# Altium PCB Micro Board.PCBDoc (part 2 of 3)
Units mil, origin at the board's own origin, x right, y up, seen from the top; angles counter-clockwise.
Board outline 8525 x 5525 mil, 2 copper layers (Top Layer, Bottom Layer); 82 components, 533 nets, 1257 pads, 165 vias.
Unrouted connection lines stored in the file: 4.
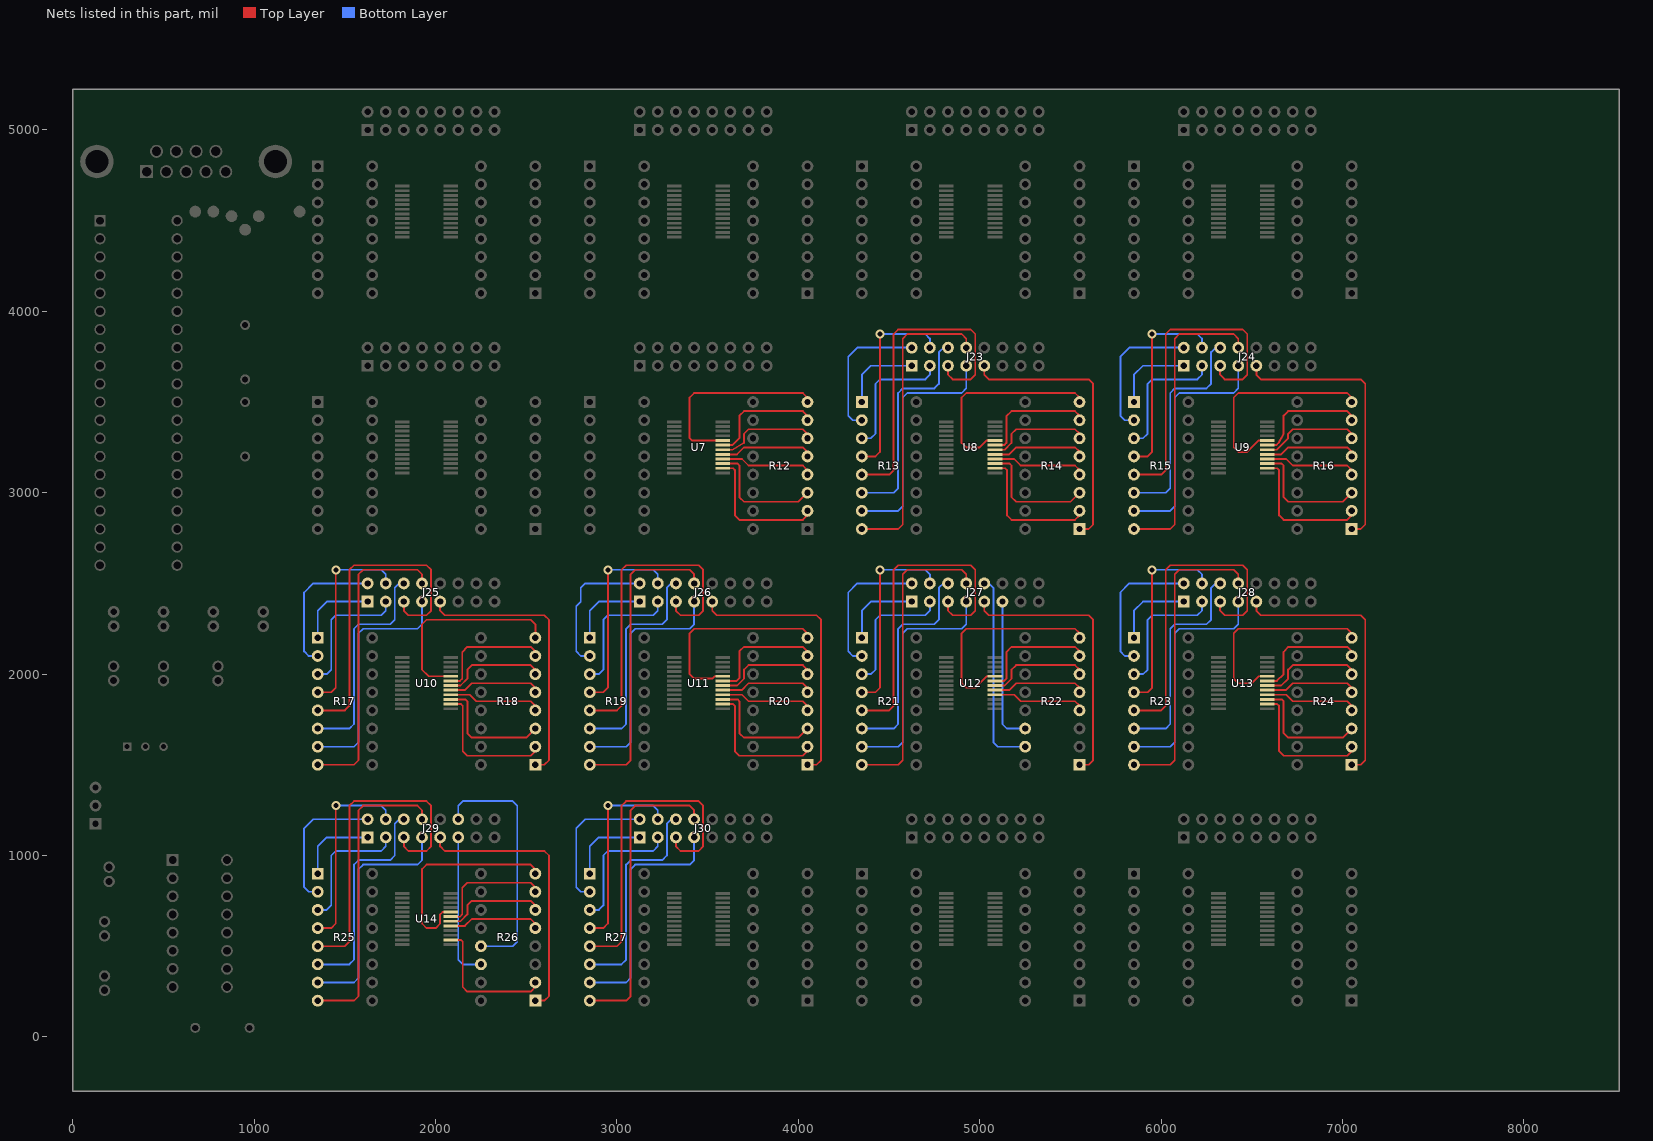
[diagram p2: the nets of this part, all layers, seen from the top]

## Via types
v1: diameter 50, hole 28, Top Layer to Bottom Layer, 165 vias

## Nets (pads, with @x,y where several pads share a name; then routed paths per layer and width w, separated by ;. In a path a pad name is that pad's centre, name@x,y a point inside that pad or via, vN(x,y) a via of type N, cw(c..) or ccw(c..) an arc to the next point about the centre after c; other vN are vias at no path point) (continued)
B90: R12.2 U7.14 | length 765.9
  Top Layer w10: U7.14@3583.86,3134.84 3640.16,3134.84 3650,3125 3650,2875 3675,2850 4025,2850 4050,2875 R12.2@4050,2900
B91: J22.11 R12.14 | length 810.4
  Bottom Layer w10: J22.11@3625,3700 3625,3025 3650,3000 R12.14@3750,3000
B91: R12.3 U7.15 | length 676.5
  Top Layer w10: U7.15@3583.86,3160.43 3664.57,3160.43 3675,3150 3675,2975 3700,2950 4000,2950 R12.3@4050,3000
B92: J22.12 R12.13 | length 1381.1
  Bottom Layer w10: J22.12@3625,3800 3625,3875 3650,3900 3925,3900 3950,3875 3950,3125 3925,3100 R12.13@3750,3100
B92: R12.4 U7.16 | length 516.4
  Top Layer w10: U7.16@3583.86,3186.02 3688.98,3186.02 3725,3150 4025,3150 4050,3125 R12.4@4050,3100
B93: J22.13 R12.12 | length 1137.1
  Bottom Layer w10: J22.13@3725,3700 3775,3750 3775,3850 3800,3875 3875,3875 3925,3825 3925,3225 3900,3200 R12.12@3750,3200
B93: R12.5 U7.17 | length 517.4
  Top Layer w10: U7.17@3583.86,3211.61 3661.61,3211.61 3700,3250 4025,3250 4050,3225 R12.5@4050,3200
B94: J22.14 R12.11 | length 581.1
  Bottom Layer w10: J22.14@3725,3800 3675,3750 3675,3325 3700,3300 R12.11@3750,3300
B94: R12.6 U7.18 | length 572.3
  Top Layer w10: U7.18@3583.86,3237.2 3637.2,3237.2 3700,3275 3700,3325 3725,3350 4025,3350 4050,3325 R12.6@4050,3300
B95: J22.15 R12.10 | length 431.1
  Bottom Layer w10: R12.10@3750,3400 3725,3400 3700,3425 3700,3550 3725,3575 3800,3575 3825,3600 J22.15@3825,3700
B95: R12.7 U7.19 | length 651.4
  Top Layer w10: U7.19@3583.86,3262.8 3634.51,3262.8 3675,3300 3675,3425 3700,3450 4025,3450 4050,3425 R12.7@4050,3400
B96: J22.16 R12.9 | length 495.7
  Bottom Layer w10: R12.9@3750,3500 3875,3500 3900,3525 3900,3775 3875,3800 J22.16@3825,3800
B96: R12.8 U7.20 | length 1109.4
  Top Layer w10: U7.20@3583.86,3288.39 3411.61,3288.39 3400,3300 3400,3525 3425,3550 4025,3550 4050,3525 R12.8@4050,3500
B97: R13.16 U8.4 | length 331.1
  Top Layer w10: R13.16@4650,3500 4700,3500 4725,3475 4725,3325 4736.02,3313.98 U8.4@4816.14,3313.98
B97: J23.1 R13.1 | length 445.7
  Bottom Layer w10: R13.1@4350,3500 4350,3650 4400,3700 J23.1@4625,3700
B98: R13.15 U8.5 | length 256.3
  Top Layer w10: R13.15@4650,3400 4675,3400 4700,3375 4700,3300 4711.61,3288.39 U8.5@4816.14,3288.39
B98: J23.2 R13.2 | length 781.1
  Bottom Layer w10: R13.2@4350,3400 4300,3400 4275,3425 4275,3750 4325,3800 J23.2@4625,3800
B99: R13.14 U8.6 | length 181.6
  Top Layer w10: R13.14@4650,3300 4687.2,3262.8 U8.6@4816.14,3262.8
B99: J23.3 R13.3 | length 731.1
  Bottom Layer w10: R13.3@4350,3300 4400,3300 4425,3325 4425,3600 4450,3625 4700,3625 4725,3650 J23.3@4725,3700
B100: R13.13 U8.7 | length 146.2
  Top Layer w10: 4675,3225 4687.2,3237.2 U8.7@4816.14,3237.2
B100: J23.4 R13.4 | length 1095.7
  Top Layer w10: R13.4@4350,3200 4425,3200 4450,3225 v1(4450,3875)
  Bottom Layer w10: v1(4450,3875) 4700,3875 4725,3850 J23.4@4725,3800
B101: R13.12 U8.8 | length 256.3
  Top Layer w10: R13.12@4650,3100 4675,3100 4700,3125 4700,3200 4711.61,3211.61 U8.8@4816.14,3211.61
B101: J23.5 R13.5 | length 1851.8
  Top Layer w10: R13.5@4350,3100 4500,3100 4525,3125 4525,3875 4550,3900 4950,3900 4975,3875 4975,3650 4950,3625 4850,3625 4825,3650 J23.5@4825,3700
B102: R13.11 U8.9 | length 331.1
  Top Layer w10: R13.11@4650,3000 4700,3000 4725,3025 4725,3175 4736.02,3186.02 U8.9@4816.14,3186.02
B102: J23.6 R13.6 | length 1216.4
  Bottom Layer w10: R13.6@4350,3000 4525,3000 4550,3025 4550,3550 4575,3575 4750,3575 4775,3600 4775,3775 4800,3800 J23.6@4825,3800
B103: R13.10 U8.10 | length 405.8
  Top Layer w10: R13.10@4650,2900 4725,2900 4750,2925 4750,3150 4760.43,3160.43 U8.10@4816.14,3160.43
B103: J23.7 R13.7 | length 1331.1
  Bottom Layer w10: R13.7@4350,2900 4550,2900 4575,2925 4575,3525 4600,3550 4900,3550 4925,3575 J23.7@4925,3700
B104: R13.9 U8.11 | length 648.3
  Top Layer w10: R13.9@4650,2800 4875,2800 4900,2825 4900,3125 4890.16,3134.84 U8.11@4816.14,3134.84
B104: J23.8 R13.8 | length 1681.1
  Top Layer w10: R13.8@4350,2800 4550,2800 4575,2825 4575,3850 4600,3875 4900,3875 4925,3850 J23.8@4925,3800
B105: R14.16 U8.13 | length 465.9
  Top Layer w10: U8.13@5083.86,3109.25 5083.86,2816.14 5100,2800 R14.16@5250,2800
B105: J23.9 R14.1 | length 1531.1
  Top Layer w10: J23.9@5025,3700 5025,3650 5050,3625 5600,3625 5625,3600 5625,2825 5600,2800 R14.1@5550,2800
B106: J23.10 R14.15 | length 1095.7
  Bottom Layer w10: J23.10@5025,3800 5050,3800 5075,3775 5075,2925 5100,2900 R14.15@5250,2900
B106: R14.2 U8.14 | length 765.9
  Top Layer w10: U8.14@5083.86,3134.84 5140.16,3134.84 5150,3125 5150,2875 5175,2850 5525,2850 5550,2875 R14.2@5550,2900
B107: J23.11 R14.14 | length 810.4
  Bottom Layer w10: J23.11@5125,3700 5125,3025 5150,3000 R14.14@5250,3000
B107: R14.3 U8.15 | length 676.5
  Top Layer w10: U8.15@5083.86,3160.43 5164.57,3160.43 5175,3150 5175,2975 5200,2950 5500,2950 R14.3@5550,3000
B108: J23.12 R14.13 | length 1381.1
  Bottom Layer w10: J23.12@5125,3800 5125,3875 5150,3900 5425,3900 5450,3875 5450,3125 5425,3100 R14.13@5250,3100
B108: R14.4 U8.16 | length 516.4
  Top Layer w10: U8.16@5083.86,3186.02 5188.98,3186.02 5225,3150 5525,3150 5550,3125 R14.4@5550,3100
B109: J23.13 R14.12 | length 1137.1
  Bottom Layer w10: J23.13@5225,3700 5275,3750 5275,3850 5300,3875 5375,3875 5425,3825 5425,3225 5400,3200 R14.12@5250,3200
B109: R14.5 U8.17 | length 517.4
  Top Layer w10: U8.17@5083.86,3211.61 5161.61,3211.61 5200,3250 5525,3250 5550,3225 R14.5@5550,3200
B110: J23.14 R14.11 | length 581.1
  Bottom Layer w10: J23.14@5225,3800 5175,3750 5175,3325 5200,3300 R14.11@5250,3300
B110: R14.6 U8.18 | length 577.5
  Top Layer w10: U8.18@5083.86,3237.2 5137.2,3237.2 5175,3275 5175,3325 5200,3350 5525,3350 5550,3325 R14.6@5550,3300
B111: J23.15 R14.10 | length 431.1
  Bottom Layer w10: R14.10@5250,3400 5225,3400 5200,3425 5200,3550 5225,3575 5300,3575 5325,3600 J23.15@5325,3700
B111: R14.7 U8.19 | length 665
  Top Layer w10: U8.19@5083.86,3262.8 5134.51,3262.8 5146.72,3275 5146.72,3421.72 5175,3450 5525,3450 5550,3425 R14.7@5550,3400
B112: J23.16 R14.9 | length 495.7
  Bottom Layer w10: R14.9@5250,3500 5375,3500 5400,3525 5400,3775 5375,3800 J23.16@5325,3800
B112: R14.8 U8.20 | length 1155.8
  Top Layer w10: U8.20@5083.86,3288.39 5038.39,3288.39 5000,3250 4925,3250 4900,3275 4900,3525 4925,3550 5525,3550 5550,3525 R14.8@5550,3500
B113: R15.16 U9.4 | length 331.1
  Top Layer w10: R15.16@6150,3500 6200,3500 6225,3475 6225,3325 6236.02,3313.98 U9.4@6316.14,3313.98
B113: J24.1 R15.1 | length 445.7
  Bottom Layer w10: R15.1@5850,3500 5850,3650 5900,3700 J24.1@6125,3700
B114: R15.15 U9.5 | length 256.3
  Top Layer w10: R15.15@6150,3400 6175,3400 6200,3375 6200,3300 6211.61,3288.39 U9.5@6316.14,3288.39
B114: J24.2 R15.2 | length 781.1
  Bottom Layer w10: R15.2@5850,3400 5800,3400 5775,3425 5775,3750 5825,3800 J24.2@6125,3800
B115: R15.14 U9.6 | length 181.6
  Top Layer w10: R15.14@6150,3300 6187.2,3262.8 U9.6@6316.14,3262.8
B115: J24.3 R15.3 | length 731.1
  Bottom Layer w10: R15.3@5850,3300 5900,3300 5925,3325 5925,3600 5950,3625 6200,3625 6225,3650 J24.3@6225,3700
B116: R15.13 U9.7 | length 146.2
  Top Layer w10: 6175,3225 6187.2,3237.2 U9.7@6316.14,3237.2
B116: J24.4 R15.4 | length 1095.7
  Top Layer w10: R15.4@5850,3200 5925,3200 5950,3225 v1(5950,3875)
  Bottom Layer w10: v1(5950,3875) 6200,3875 6225,3850 J24.4@6225,3800
B117: R15.12 U9.8 | length 256.3
  Top Layer w10: R15.12@6150,3100 6175,3100 6200,3125 6200,3200 6211.61,3211.61 U9.8@6316.14,3211.61
B117: J24.5 R15.5 | length 1851.8
  Top Layer w10: R15.5@5850,3100 6000,3100 6025,3125 6025,3875 6050,3900 6450,3900 6475,3875 6475,3650 6450,3625 6350,3625 6325,3650 J24.5@6325,3700
B118: R15.11 U9.9 | length 331.1
  Top Layer w10: R15.11@6150,3000 6200,3000 6225,3025 6225,3175 6236.02,3186.02 U9.9@6316.14,3186.02
B118: J24.6 R15.6 | length 1216.4
  Bottom Layer w10: R15.6@5850,3000 6025,3000 6050,3025 6050,3550 6075,3575 6250,3575 6275,3600 6275,3775 6300,3800 J24.6@6325,3800
B119: R15.10 U9.10 | length 405.8
  Top Layer w10: R15.10@6150,2900 6225,2900 6250,2925 6250,3150 6260.43,3160.43 U9.10@6316.14,3160.43
B119: J24.7 R15.7 | length 1331.1
  Bottom Layer w10: R15.7@5850,2900 6050,2900 6075,2925 6075,3525 6100,3550 6400,3550 6425,3575 J24.7@6425,3700
B120: R15.9 U9.11 | length 648.3
  Top Layer w10: R15.9@6150,2800 6375,2800 6400,2825 6400,3125 6390.16,3134.84 U9.11@6316.14,3134.84
B120: J24.8 R15.8 | length 1681.1
  Top Layer w10: R15.8@5850,2800 6050,2800 6075,2825 6075,3850 6100,3875 6400,3875 6425,3850 J24.8@6425,3800
B121: R16.16 U9.13 | length 465.9
  Top Layer w10: U9.13@6583.86,3109.25 6583.86,2816.14 6600,2800 R16.16@6750,2800
B121: J24.9 R16.1 | length 1531.1
  Top Layer w10: J24.9@6525,3700 6525,3650 6550,3625 7100,3625 7125,3600 7125,2825 7100,2800 R16.1@7050,2800
B122: J24.10 R16.15 | length 1095.7
  Bottom Layer w10: J24.10@6525,3800 6550,3800 6575,3775 6575,2925 6600,2900 R16.15@6750,2900
B122: R16.2 U9.14 | length 765.9
  Top Layer w10: U9.14@6583.86,3134.84 6640.16,3134.84 6650,3125 6650,2875 6675,2850 7025,2850 7050,2875 R16.2@7050,2900
B123: J24.11 R16.14 | length 810.4
  Bottom Layer w10: J24.11@6625,3700 6625,3025 6650,3000 R16.14@6750,3000
B123: R16.3 U9.15 | length 676.5
  Top Layer w10: U9.15@6583.86,3160.43 6664.57,3160.43 6675,3150 6675,2975 6700,2950 7000,2950 R16.3@7050,3000
B124: J24.12 R16.13 | length 1381.1
  Bottom Layer w10: J24.12@6625,3800 6625,3875 6650,3900 6925,3900 6950,3875 6950,3125 6925,3100 R16.13@6750,3100
B124: R16.4 U9.16 | length 516.4
  Top Layer w10: U9.16@6583.86,3186.02 6688.98,3186.02 6725,3150 7025,3150 7050,3125 R16.4@7050,3100
B125: J24.13 R16.12 | length 1137.1
  Bottom Layer w10: J24.13@6725,3700 6775,3750 6775,3850 6800,3875 6875,3875 6925,3825 6925,3225 6900,3200 R16.12@6750,3200
B125: R16.5 U9.17 | length 517.4
  Top Layer w10: U9.17@6583.86,3211.61 6661.61,3211.61 6700,3250 7025,3250 7050,3225 R16.5@7050,3200
B126: J24.14 R16.11 | length 581.1
  Bottom Layer w10: J24.14@6725,3800 6675,3750 6675,3325 6700,3300 R16.11@6750,3300
B126: R16.6 U9.18 | length 562.9
  Top Layer w10: U9.18@6583.86,3237.2 6637.2,3237.2 6700,3300 6700,3325 6725,3350 7025,3350 7050,3325 R16.6@7050,3300
B127: J24.15 R16.10 | length 431.1
  Bottom Layer w10: R16.10@6750,3400 6725,3400 6700,3425 6700,3550 6725,3575 6800,3575 6825,3600 J24.15@6825,3700
B127: R16.7 U9.19 | length 646.1
  Top Layer w10: U9.19@6583.86,3262.8 6634.51,3262.8 6646.72,3275 6675,3325 6675,3425 6700,3450 7025,3450 7050,3425 R16.7@7050,3400
B128: J24.16 R16.9 | length 495.7
  Bottom Layer w10: R16.9@6750,3500 6875,3500 6900,3525 6900,3775 6875,3800 J24.16@6825,3800
B128: R16.8 U9.20 | length 1191.2
  Top Layer w10: U9.20@6583.86,3288.39 6538.39,3288.39 6475,3225 6425,3225 6400,3250 6400,3525 6425,3550 7025,3550 7050,3525 R16.8@7050,3500
B129: R17.16 U10.4 | length 331.1
  Top Layer w10: R17.16@1650,2200 1700,2200 1725,2175 1725,2025 1736.02,2013.98 U10.4@1816.14,2013.98
B129: J25.1 R17.1 | length 445.7
  Bottom Layer w10: R17.1@1350,2200 1350,2350 1400,2400 J25.1@1625,2400
B130: R17.15 U10.5 | length 256.3
  Top Layer w10: R17.15@1650,2100 1675,2100 1700,2075 1700,2000 1711.61,1988.39 U10.5@1816.14,1988.39
B130: J25.2 R17.2 | length 781.1
  Bottom Layer w10: R17.2@1350,2100 1300,2100 1275,2125 1275,2450 1325,2500 J25.2@1625,2500
B131: R17.14 U10.6 | length 181.6
  Top Layer w10: R17.14@1650,2000 1687.2,1962.8 U10.6@1816.14,1962.8
B131: J25.3 R17.3 | length 781.1
  Bottom Layer w10: R17.3@1325,2000 R17.3@1375,2000 ; R17.3@1350,2000 1400,2000 1425,2025 1425,2300 1450,2325 1700,2325 1725,2350 J25.3@1725,2400
B132: R17.13 U10.7 | length 146.2
  Top Layer w10: 1675,1925 1687.2,1937.2 U10.7@1816.14,1937.2
B132: J25.4 R17.4 | length 1095.7
  Top Layer w10: R17.4@1350,1900 1425,1900 1450,1925 v1(1450,2575)
  Bottom Layer w10: v1(1450,2575) 1700,2575 1725,2550 J25.4@1725,2500
B133: R17.12 U10.8 | length 281.3
  Top Layer w10: R17.12@1625,1800 R17.12@1650,1800 1675,1800 1700,1825 1700,1900 1711.61,1911.61 U10.8@1816.14,1911.61
B133: J25.5 R17.5 | length 1851.8
  Top Layer w10: R17.5@1350,1800 1500,1800 1525,1825 1525,2575 1550,2600 1950,2600 1975,2575 1975,2350 1950,2325 1850,2325 1825,2350 J25.5@1825,2400
B134: R17.11 U10.9 | length 331.1
  Top Layer w10: R17.11@1650,1700 1700,1700 1725,1725 1725,1875 1736.02,1886.02 U10.9@1816.14,1886.02
B134: J25.6 R17.6 | length 1216.4
  Bottom Layer w10: R17.6@1350,1700 1525,1700 1550,1725 1550,2250 1575,2275 1750,2275 1775,2300 1775,2475 1800,2500 J25.6@1825,2500
B135: R17.10 U10.10 | length 405.8
  Top Layer w10: R17.10@1650,1600 1725,1600 1750,1625 1750,1850 1760.43,1860.43 U10.10@1816.14,1860.43
B135: J25.7 R17.7 | length 1331.1
  Bottom Layer w10: R17.7@1350,1600 1550,1600 1575,1625 1575,2225 1600,2250 1900,2250 1925,2275 J25.7@1925,2400
B136: R17.9 U10.11 | length 648.3
  Top Layer w10: R17.9@1650,1500 1875,1500 1900,1525 1900,1825 1890.16,1834.84 U10.11@1816.14,1834.84
B136: J25.8 R17.8 | length 1681.1
  Top Layer w10: R17.8@1350,1500 1550,1500 1575,1525 1575,2550 1600,2575 1900,2575 1925,2550 J25.8@1925,2500
B137: R18.16 U10.13 | length 465.9
  Top Layer w10: U10.13@2083.86,1809.25 2083.86,1516.14 2100,1500 R18.16@2250,1500
B137: J25.9 R18.1 | length 1531.1
  Top Layer w10: J25.9@2025,2400 2025,2350 2050,2325 2600,2325 2625,2300 2625,1525 2600,1500 R18.1@2550,1500
B138: J25.10 R18.15 | length 1095.7
  Bottom Layer w10: J25.10@2025,2500 2050,2500 2075,2475 2075,1625 2100,1600 R18.15@2250,1600
B138: R18.2 U10.14 | length 765.9
  Top Layer w10: U10.14@2083.86,1834.84 2140.16,1834.84 2150,1825 2150,1575 2175,1550 2525,1550 2550,1575 R18.2@2550,1600
B139: J25.11 R18.14 | length 810.4
  Bottom Layer w10: J25.11@2125,2400 2125,1725 2150,1700 R18.14@2250,1700
B139: R18.3 U10.15 | length 676.5
  Top Layer w10: U10.15@2083.86,1860.43 2164.57,1860.43 2175,1850 2175,1675 2200,1650 2500,1650 R18.3@2550,1700
B140: J25.12 R18.13 | length 1381.1
  Bottom Layer w10: J25.12@2125,2500 2125,2575 2150,2600 2425,2600 2450,2575 2450,1825 2425,1800 R18.13@2250,1800
B140: R18.4 U10.16 | length 516.4
  Top Layer w10: U10.16@2083.86,1886.02 2188.98,1886.02 2225,1850 2525,1850 2550,1825 R18.4@2550,1800
B141: J25.13 R18.12 | length 1137.1
  Bottom Layer w10: J25.13@2225,2400 2275,2450 2275,2550 2300,2575 2375,2575 2425,2525 2425,1925 2400,1900 R18.12@2250,1900
B141: R18.5 U10.17 | length 517.4
  Top Layer w10: U10.17@2083.86,1911.61 2161.61,1911.61 2200,1950 2525,1950 2550,1925 R18.5@2550,1900
B142: J25.14 R18.11 | length 581.1
  Bottom Layer w10: J25.14@2225,2500 2175,2450 2175,2025 2200,2000 R18.11@2250,2000
B142: R18.6 U10.18 | length 577.5
  Top Layer w10: U10.18@2083.86,1937.2 2137.2,1937.2 2175,1975 2175,2025 2200,2050 2525,2050 2550,2025 R18.6@2550,2000
B143: J25.15 R18.10 | length 431.1
  Bottom Layer w10: R18.10@2250,2100 2225,2100 2200,2125 2200,2250 2225,2275 2300,2275 2325,2300 J25.15@2325,2400
B143: R18.7 U10.19 | length 665
  Top Layer w10: U10.19@2083.86,1962.8 2134.51,1962.8 2146.72,1975 2146.72,2121.72 2175,2150 2525,2150 2550,2125 R18.7@2550,2100
B144: J25.16 R18.9 | length 495.7
  Bottom Layer w10: R18.9@2250,2200 2375,2200 2400,2225 2400,2475 2375,2500 J25.16@2325,2500
B144: R18.8 U10.20 | length 1144.7
  Top Layer w10: U10.20@2083.86,1988.39 1961.61,1988.39 1925,2025 1925,2275 1950,2300 2525,2300 2550,2275 2550,2225 R18.8@2550,2200
B145: R19.16 U11.4 | length 331.1
  Top Layer w10: R19.16@3150,2200 3200,2200 3225,2175 3225,2025 3236.02,2013.98 U11.4@3316.14,2013.98
B145: J26.1 R19.1 | length 445.7
  Bottom Layer w10: R19.1@2850,2200 2850,2350 2900,2400 J26.1@3125,2400
B146: R19.15 U11.5 | length 256.3
  Top Layer w10: R19.15@3150,2100 3175,2100 3200,2075 3200,2000 3211.61,1988.39 U11.5@3316.14,1988.39
B146: J26.2 R19.2 | length 781.1
  Bottom Layer w10: R19.2@2850,2100 2800,2100 2775,2125 2775,2375 2800,2400 2800,2475 2825,2500 J26.2@3125,2500
B147: R19.14 U11.6 | length 181.6
  Top Layer w10: R19.14@3150,2000 3187.2,1962.8 U11.6@3316.14,1962.8
B147: J26.3 R19.3 | length 731.1
  Bottom Layer w10: R19.3@2850,2000 2900,2000 2925,2025 2925,2300 2950,2325 3200,2325 3225,2350 J26.3@3225,2400
B148: R19.13 U11.7 | length 146.2
  Top Layer w10: 3175,1925 3187.2,1937.2 U11.7@3316.14,1937.2
B148: J26.4 R19.4 | length 1095.7
  Top Layer w10: R19.4@2850,1900 2925,1900 2950,1925 v1(2950,2575)
  Bottom Layer w10: v1(2950,2575) 3200,2575 3225,2550 J26.4@3225,2500
B149: R19.12 U11.8 | length 256.3
  Top Layer w10: R19.12@3150,1800 3175,1800 3200,1825 3200,1900 3211.61,1911.61 U11.8@3316.14,1911.61
B149: J26.5 R19.5 | length 1851.8
  Top Layer w10: R19.5@2850,1800 3000,1800 3025,1825 3025,2575 3050,2600 3450,2600 3475,2575 3475,2350 3450,2325 3350,2325 3325,2350 J26.5@3325,2400
B150: R19.11 U11.9 | length 331.1
  Top Layer w10: R19.11@3150,1700 3200,1700 3225,1725 3225,1875 3236.02,1886.02 U11.9@3316.14,1886.02
B150: J26.6 R19.6 | length 1216.4
  Bottom Layer w10: R19.6@2850,1700 3025,1700 3050,1725 3050,2250 3075,2275 3250,2275 3275,2300 3275,2475 3300,2500 J26.6@3325,2500
B151: R19.10 U11.10 | length 405.8
  Top Layer w10: R19.10@3150,1600 3225,1600 3250,1625 3250,1850 3260.43,1860.43 U11.10@3316.14,1860.43
B151: J26.7 R19.7 | length 1331.1
  Bottom Layer w10: R19.7@2850,1600 3050,1600 3075,1625 3075,2225 3100,2250 3400,2250 3425,2275 J26.7@3425,2400
B152: R19.9 U11.11 | length 598.3
  Top Layer w10: R19.9@3150,1500 3350,1500 3375,1525 3375,1825 3365.16,1834.84 U11.11@3316.14,1834.84
B152: J26.8 R19.8 | length 1681.1
  Top Layer w10: R19.8@2850,1500 3050,1500 3075,1525 3075,2550 3100,2575 3400,2575 3425,2550 J26.8@3425,2500
B153: R20.16 U11.13 | length 465.9
  Top Layer w10: U11.13@3583.86,1809.25 3583.86,1516.14 3600,1500 R20.16@3750,1500
B153: J26.9 R20.1 | length 1531.1
  Top Layer w10: J26.9@3525,2400 3525,2350 3550,2325 4100,2325 4125,2300 4125,1525 4100,1500 R20.1@4050,1500
B154: J26.10 R20.15 | length 1095.7
  Bottom Layer w10: J26.10@3525,2500 3550,2500 3575,2475 3575,1625 3600,1600 R20.15@3750,1600
B154: R20.2 U11.14 | length 765.9
  Top Layer w10: U11.14@3583.86,1834.84 3640.16,1834.84 3650,1825 3650,1575 3675,1550 4025,1550 4050,1575 R20.2@4050,1600
B155: J26.11 R20.14 | length 810.4
  Bottom Layer w10: J26.11@3625,2400 3625,1725 3650,1700 R20.14@3750,1700
B155: R20.3 U11.15 | length 676.5
  Top Layer w10: U11.15@3583.86,1860.43 3664.57,1860.43 3675,1850 3675,1675 3700,1650 4000,1650 R20.3@4050,1700
B156: J26.12 R20.13 | length 1381.1
  Bottom Layer w10: J26.12@3625,2500 3625,2575 3650,2600 3925,2600 3950,2575 3950,1825 3925,1800 R20.13@3750,1800
B156: R20.4 U11.16 | length 516.4
  Top Layer w10: U11.16@3583.86,1886.02 3688.98,1886.02 3725,1850 4025,1850 4050,1825 R20.4@4050,1800
B157: J26.13 R20.12 | length 1137.1
  Bottom Layer w10: J26.13@3725,2400 3775,2450 3775,2550 3800,2575 3875,2575 3925,2525 3925,1925 3900,1900 R20.12@3750,1900
B157: R20.5 U11.17 | length 517.4
  Top Layer w10: U11.17@3583.86,1911.61 3686.61,1911.61 3725,1950 4025,1950 4050,1925 R20.5@4050,1900
B158: J26.14 R20.11 | length 581.1
  Bottom Layer w10: J26.14@3725,2500 3675,2450 3675,2025 3700,2000 R20.11@3750,2000
B158: R20.6 U11.18 | length 577.5
  Top Layer w10: U11.18@3583.86,1937.2 3662.2,1937.2 3700,1975 3700,2025 3725,2050 4025,2050 4050,2025 R20.6@4050,2000
B159: J26.15 R20.10 | length 431.1
  Bottom Layer w10: R20.10@3750,2100 3725,2100 3700,2125 3700,2250 3725,2275 3800,2275 3825,2300 J26.15@3825,2400
B159: R20.7 U11.19 | length 665
  Top Layer w10: U11.19@3583.86,1962.8 3659.51,1962.8 3675,1978.28 3675,2125 3700,2150 4025,2150 4050,2125 R20.7@4050,2100
B160: J26.16 R20.9 | length 495.7
  Bottom Layer w10: R20.9@3750,2200 3875,2200 3900,2225 3900,2475 3875,2500 J26.16@3825,2500
B160: R20.8 U11.20 | length 1120.5
  Top Layer w10: U11.20@3583.86,1988.39 3538.39,1988.39 3525,1975 3425,1975 3400,2000 3400,2225 3425,2250 4025,2250 4050,2225 R20.8@4050,2200
B161: R21.16 U12.4 | length 331.1
  Top Layer w10: R21.16@4650,2200 4700,2200 4725,2175 4725,2025 4736.02,2013.98 U12.4@4816.14,2013.98
B161: J27.1 R21.1 | length 445.7
  Bottom Layer w10: R21.1@4350,2200 4350,2350 4400,2400 J27.1@4625,2400
B162: R21.15 U12.5 | length 256.3
  Top Layer w10: R21.15@4650,2100 4675,2100 4700,2075 4700,2000 4711.61,1988.39 U12.5@4816.14,1988.39
B162: J27.2 R21.2 | length 781.1
  Bottom Layer w10: R21.2@4350,2100 4300,2100 4275,2125 4275,2450 4325,2500 J27.2@4625,2500
B163: R21.14 U12.6 | length 181.6
  Top Layer w10: R21.14@4650,2000 4687.2,1962.8 U12.6@4816.14,1962.8
B163: J27.3 R21.3 | length 731.1
  Bottom Layer w10: R21.3@4350,2000 4400,2000 4425,2025 4425,2300 4450,2325 4700,2325 4725,2350 J27.3@4725,2400
B164: R21.13 U12.7 | length 146.2
  Top Layer w10: 4675,1925 4687.2,1937.2 U12.7@4816.14,1937.2
B164: J27.4 R21.4 | length 1095.7
  Top Layer w10: R21.4@4350,1900 4425,1900 4450,1925 v1(4450,2575)
  Bottom Layer w10: v1(4450,2575) 4700,2575 4725,2550 J27.4@4725,2500
B165: R21.12 U12.8 | length 256.3
  Top Layer w10: R21.12@4650,1800 4675,1800 4700,1825 4700,1900 4711.61,1911.61 U12.8@4816.14,1911.61
B165: J27.5 R21.5 | length 1851.8
  Top Layer w10: R21.5@4350,1800 4500,1800 4525,1825 4525,2575 4550,2600 4950,2600 4975,2575 4975,2350 4950,2325 4850,2325 4825,2350 J27.5@4825,2400
B166: R21.11 U12.9 | length 331.1
  Top Layer w10: R21.11@4650,1700 4700,1700 4725,1725 4725,1875 4736.02,1886.02 U12.9@4816.14,1886.02
B166: J27.6 R21.6 | length 1216.4
  Bottom Layer w10: R21.6@4350,1700 4525,1700 4550,1725 4550,2250 4575,2275 4750,2275 4775,2300 4775,2475 4800,2500 J27.6@4825,2500
B167: R21.10 U12.10 | length 405.8
  Top Layer w10: R21.10@4650,1600 4725,1600 4750,1625 4750,1850 4760.43,1860.43 U12.10@4816.14,1860.43
B167: J27.7 R21.7 | length 1331.1
  Bottom Layer w10: R21.7@4350,1600 4550,1600 4575,1625 4575,2225 4600,2250 4900,2250 4925,2275 J27.7@4925,2400
B168: R21.9 U12.11 | length 648.3
  Top Layer w10: R21.9@4650,1500 4875,1500 4900,1525 4900,1825 4890.16,1834.84 U12.11@4816.14,1834.84
B168: J27.8 R21.8 | length 1681.1
  Top Layer w10: R21.8@4350,1500 4550,1500 4575,1525 4575,2550 4600,2575 4900,2575 4925,2550 J27.8@4925,2500
B169: R22.16 U12.13 | length 465.9
  Top Layer w10: U12.13@5083.86,1809.25 5083.86,1516.14 5100,1500 R22.16@5250,1500
B169: J27.9 R22.1 | length 1531.1
  Top Layer w10: J27.9@5025,2400 5025,2350 5050,2325 5600,2325 5625,2300 5625,1525 5600,1500 R22.1@5550,1500
B170: R22.2 U12.14 | length 765.9
  Top Layer w10: U12.14@5083.86,1834.84 5140.16,1834.84 5150,1825 5150,1575 5175,1550 5525,1550 5550,1575 R22.2@5550,1600
B170: J27.10 R22.15 | length 1095.7
  Bottom Layer w10: J27.10@5025,2500 5050,2500 5075,2475 5075,1625 5100,1600 R22.15@5250,1600
B171: R22.3 U12.15 | length 676.5
  Top Layer w10: U12.15@5083.86,1860.43 5164.57,1860.43 5175,1850 5175,1675 5200,1650 5500,1650 R22.3@5550,1700
B171: J27.11 R22.14 | length 810.4
  Bottom Layer w10: J27.11@5125,2400 5125,1725 5150,1700 R22.14@5250,1700
B172: J27.12 R22.13 | length 1381.1
  Bottom Layer w10: J27.12@5125,2500 5125,2575 5150,2600 5425,2600 5450,2575 5450,1825 5425,1800 R22.13@5250,1800
B172: R22.4 U12.16 | length 516.4
  Top Layer w10: U12.16@5083.86,1886.02 5188.98,1886.02 5225,1850 5525,1850 5550,1825 R22.4@5550,1800
B173: J27.13 R22.12 | length 1137.1
  Bottom Layer w10: J27.13@5225,2400 5275,2450 5275,2550 5300,2575 5375,2575 5425,2525 5425,1925 5400,1900 R22.12@5250,1900
B173: R22.5 U12.17 | length 517.4
  Top Layer w10: U12.17@5083.86,1911.61 5161.61,1911.61 5200,1950 5525,1950 5550,1925 R22.5@5550,1900
B174: J27.14 R22.11 | length 581.1
  Bottom Layer w10: J27.14@5225,2500 5175,2450 5175,2025 5200,2000 R22.11@5250,2000
B174: R22.6 U12.18 | length 577.5
  Top Layer w10: U12.18@5083.86,1937.2 5137.2,1937.2 5175,1975 5175,2025 5200,2050 5525,2050 5550,2025 R22.6@5550,2000
B175: J27.15 R22.10 | length 431.1
  Bottom Layer w10: R22.10@5250,2100 5225,2100 5200,2125 5200,2250 5225,2275 5300,2275 5325,2300 J27.15@5325,2400
B175: R22.7 U12.19 | length 665
  Top Layer w10: U12.19@5083.86,1962.8 5134.51,1962.8 5146.72,1975 5146.72,2121.72 5175,2150 5525,2150 5550,2125 R22.7@5550,2100
B176: J27.16 R22.9 | length 495.7
  Bottom Layer w10: R22.9@5250,2200 5375,2200 5400,2225 5400,2475 5375,2500 J27.16@5325,2500
B176: R22.8 U12.20 | length 1191.2
  Top Layer w10: U12.20@5083.86,1988.39 5038.39,1988.39 4975,1925 4925,1925 4900,1950 4900,1975 4900,2225 4925,2250 5525,2250 5550,2225 R22.8@5550,2200
B177: R23.16 U13.4 | length 331.1
  Top Layer w10: R23.16@6150,2200 6200,2200 6225,2175 6225,2025 6236.02,2013.98 U13.4@6316.14,2013.98
B177: J28.1 R23.1 | length 445.7
  Bottom Layer w10: R23.1@5850,2200 5850,2350 5900,2400 J28.1@6125,2400
B178: R23.15 U13.5 | length 256.3
  Top Layer w10: R23.15@6150,2100 6175,2100 6200,2075 6200,2000 6211.61,1988.39 U13.5@6316.14,1988.39
B178: J28.2 R23.2 | length 781.1
  Bottom Layer w10: R23.2@5850,2100 5800,2100 5775,2125 5775,2450 5825,2500 J28.2@6125,2500
B179: R23.14 U13.6 | length 181.6
  Top Layer w10: R23.14@6150,2000 6187.2,1962.8 U13.6@6316.14,1962.8
B179: J28.3 R23.3 | length 731.1
  Bottom Layer w10: R23.3@5850,2000 5900,2000 5925,2025 5925,2300 5950,2325 6200,2325 6225,2350 J28.3@6225,2400
B180: R23.13 U13.7 | length 146.2
  Top Layer w10: 6175,1925 6187.2,1937.2 U13.7@6316.14,1937.2
B180: J28.4 R23.4 | length 1095.7
  Top Layer w10: R23.4@5850,1900 5925,1900 5950,1925 v1(5950,2575)
  Bottom Layer w10: v1(5950,2575) 6200,2575 6225,2550 J28.4@6225,2500
B181: R23.12 U13.8 | length 256.3
  Top Layer w10: R23.12@6150,1800 6175,1800 6200,1825 6200,1900 6211.61,1911.61 U13.8@6316.14,1911.61
B181: J28.5 R23.5 | length 1851.8
  Top Layer w10: R23.5@5850,1800 6000,1800 6025,1825 6025,2575 6050,2600 6450,2600 6475,2575 6475,2350 6450,2325 6350,2325 6325,2350 J28.5@6325,2400
B182: R23.11 U13.9 | length 331.1
  Top Layer w10: R23.11@6150,1700 6200,1700 6225,1725 6225,1875 6236.02,1886.02 U13.9@6316.14,1886.02
B182: J28.6 R23.6 | length 1216.4
  Bottom Layer w10: R23.6@5850,1700 6025,1700 6050,1725 6050,2250 6075,2275 6250,2275 6275,2300 6275,2475 6300,2500 J28.6@6325,2500
B183: R23.10 U13.10 | length 405.8
  Top Layer w10: R23.10@6150,1600 6225,1600 6250,1625 6250,1850 6260.43,1860.43 U13.10@6316.14,1860.43
B183: J28.7 R23.7 | length 1331.1
  Bottom Layer w10: R23.7@5850,1600 6050,1600 6075,1625 6075,2225 6100,2250 6400,2250 6425,2275 J28.7@6425,2400
B184: R23.9 U13.11 | length 648.3
  Top Layer w10: R23.9@6150,1500 6375,1500 6400,1525 6400,1825 6390.16,1834.84 U13.11@6316.14,1834.84
B184: J28.8 R23.8 | length 1681.1
  Top Layer w10: R23.8@5850,1500 6050,1500 6075,1525 6075,2550 6100,2575 6400,2575 6425,2550 J28.8@6425,2500
B185: R24.16 U13.13 | length 465.9
  Top Layer w10: U13.13@6583.86,1809.25 6583.86,1516.14 6600,1500 R24.16@6750,1500
B185: J28.9 R24.1 | length 1531.1
  Top Layer w10: J28.9@6525,2400 6525,2350 6550,2325 7100,2325 7125,2300 7125,1525 7100,1500 R24.1@7050,1500
B186: J28.10 R24.15 | length 1095.7
  Bottom Layer w10: J28.10@6525,2500 6550,2500 6575,2475 6575,1625 6600,1600 R24.15@6750,1600
B186: R24.2 U13.14 | length 765.9
  Top Layer w10: U13.14@6583.86,1834.84 6640.16,1834.84 6650,1825 6650,1575 6675,1550 7025,1550 7050,1575 R24.2@7050,1600
B187: J28.11 R24.14 | length 810.4
  Bottom Layer w10: J28.11@6625,2400 6625,1725 6650,1700 R24.14@6750,1700
B187: R24.3 U13.15 | length 676.5
  Top Layer w10: U13.15@6583.86,1860.43 6664.57,1860.43 6675,1850 6675,1675 6700,1650 7000,1650 R24.3@7050,1700
B188: J28.12 R24.13 | length 1381.1
  Bottom Layer w10: J28.12@6625,2500 6625,2575 6650,2600 6925,2600 6950,2575 6950,1825 6925,1800 R24.13@6750,1800
B188: R24.4 U13.16 | length 516.4
  Top Layer w10: U13.16@6583.86,1886.02 6688.98,1886.02 6725,1850 7025,1850 7050,1825 R24.4@7050,1800
B189: J28.13 R24.12 | length 1137.1
  Bottom Layer w10: J28.13@6725,2400 6775,2450 6775,2550 6800,2575 6875,2575 6925,2525 6925,1925 6900,1900 R24.12@6750,1900
B189: R24.5 U13.17 | length 517.4
  Top Layer w10: U13.17@6583.86,1911.61 6686.61,1911.61 6725,1950 7025,1950 7050,1925 R24.5@7050,1900
B190: J28.14 R24.11 | length 581.1
  Bottom Layer w10: J28.14@6725,2500 6675,2450 6675,2025 6700,2000 R24.11@6750,2000
B190: R24.6 U13.18 | length 577.5
  Top Layer w10: U13.18@6583.86,1937.2 6662.2,1937.2 6700,1975 6700,2025 6725,2050 7025,2050 7050,2025 R24.6@7050,2000
B191: J28.15 R24.10 | length 431.1
  Bottom Layer w10: R24.10@6750,2100 6725,2100 6700,2125 6700,2250 6725,2275 6800,2275 6825,2300 J28.15@6825,2400
B191: R24.7 U13.19 | length 651.4
  Top Layer w10: U13.19@6583.86,1962.8 6637.8,1962.8 6675,2000 6675,2121.72 6700,2150 7025,2150 7050,2125 R24.7@7050,2100
B192: J28.16 R24.9 | length 495.7
  Bottom Layer w10: R24.9@6750,2200 6875,2200 6900,2225 6900,2475 6875,2500 J28.16@6825,2500
B192: R24.8 U13.20 | length 1155.8
  Top Layer w10: U13.20@6583.86,1988.39 6538.39,1988.39 6500,1950 6425,1950 6400,1975 6400,2225 6425,2250 7025,2250 7050,2225 R24.8@7050,2200
B193: R25.16 U14.4 | length 331.1
  Top Layer w10: R25.16@1650,900 1700,900 1725,875 1725,725 1736.02,713.98 U14.4@1816.14,713.98
B193: J29.1 R25.1 | length 445.7
  Bottom Layer w10: R25.1@1350,900 1350,1050 1400,1100 J29.1@1625,1100
B194: R25.15 U14.5 | length 256.3
  Top Layer w10: R25.15@1650,800 1675,800 1700,775 1700,700 1711.61,688.39 U14.5@1816.14,688.39
B194: J29.2 R25.2 | length 781.1
  Bottom Layer w10: R25.2@1350,800 1300,800 1275,825 1275,1150 1325,1200 J29.2@1625,1200
B195: R25.14 U14.6 | length 181.6
  Top Layer w10: R25.14@1650,700 1687.2,662.8 U14.6@1816.14,662.8
B195: J29.3 R25.3 | length 731.1
  Bottom Layer w10: R25.3@1350,700 1400,700 1425,725 1425,1000 1450,1025 1700,1025 1725,1050 J29.3@1725,1100
B196: R25.13 U14.7 | length 146.2
  Top Layer w10: 1675,625 1687.2,637.2 U14.7@1816.14,637.2
B196: J29.4 R25.4 | length 1095.7
  Top Layer w10: R25.4@1350,600 1425,600 1450,625 v1(1450,1275)
  Bottom Layer w10: v1(1450,1275) 1700,1275 1725,1250 J29.4@1725,1200
B197: R25.12 U14.8 | length 256.3
  Top Layer w10: R25.12@1650,500 1675,500 1700,525 1700,600 1711.61,611.61 U14.8@1816.14,611.61
B197: J29.5 R25.5 | length 1851.8
  Top Layer w10: R25.5@1350,500 1500,500 1525,525 1525,1275 1550,1300 1950,1300 1975,1275 1975,1050 1950,1025 1850,1025 1825,1050 J29.5@1825,1100
B198: R25.11 U14.9 | length 331.1
  Top Layer w10: R25.11@1650,400 1700,400 1725,425 1725,575 1736.02,586.02 U14.9@1816.14,586.02
B198: J29.6 R25.6 | length 1216.4
  Bottom Layer w10: R25.6@1350,400 1525,400 1550,425 1550,950 1575,975 1750,975 1775,1000 1775,1175 1800,1200 J29.6@1825,1200
B199: R25.10 U14.10 | length 405.8
  Top Layer w10: R25.10@1650,300 1725,300 1750,325 1750,550 1760.43,560.43 U14.10@1816.14,560.43
B199: J29.7 R25.7 | length 1331.1
  Bottom Layer w10: R25.7@1350,300 1550,300 1575,325 1575,925 1600,950 1900,950 1925,975 J29.7@1925,1100
B200: R25.9 U14.11 | length 648.3
  Top Layer w10: R25.9@1650,200 1875,200 1900,225 1900,525 1890.16,534.84 U14.11@1816.14,534.84
B200: J29.8 R25.8 | length 1681.1
  Top Layer w10: R25.8@1350,200 1550,200 1575,225 1575,1250 1600,1275 1900,1275 1925,1250 J29.8@1925,1200
B201: R26.16 U14.13 | length 465.9
  Top Layer w10: U14.13@2083.86,509.25 2083.86,216.14 2100,200 R26.16@2250,200
B201: J29.9 R26.1 | length 1531.1
  Top Layer w10: J29.9@2025,1100 2025,1050 2050,1025 2600,1025 2625,1000 2625,225 2600,200 R26.1@2550,200
B202: J29.10 R26.15 | length 1095.7
  Bottom Layer w10: J29.10@2025,1200 2050,1200 2075,1175 2075,325 2100,300 R26.15@2250,300
B202: R26.2 U14.14 | length 765.9
  Top Layer w10: U14.14@2083.86,534.84 2140.16,534.84 2150,525 2150,275 2175,250 2525,250 2550,275 R26.2@2550,300
B203: R26.3 U14.15 | length 676.5
  Top Layer w10: U14.15@2083.86,560.43 2164.57,560.43 2175,550 2175,375 2200,350 2500,350 R26.3@2550,400
B203: J29.11 R26.14 | length 810.4
  Bottom Layer w10: J29.11@2125,1100 2125,425 2150,400 R26.14@2250,400
B204: R26.4 U14.16 | length 516.4
  Top Layer w10: U14.16@2083.86,586.02 2188.98,586.02 2225,550 2525,550 2550,525 R26.4@2550,500
B204: J29.12 R26.13 | length 1381.1
  Bottom Layer w10: J29.12@2125,1200 2125,1275 2150,1300 2425,1300 2450,1275 2450,525 2425,500 R26.13@2250,500
B205: J29.13 R26.12 | length 1137.1
  Bottom Layer w10: J29.13@2225,1100 2275,1150 2275,1250 2300,1275 2375,1275 2425,1225 2425,625 2400,600 R26.12@2250,600
B205: R26.5 U14.17 | length 517.4
  Top Layer w10: U14.17@2083.86,611.61 2161.61,611.61 2200,650 2525,650 2550,625 R26.5@2550,600
B206: J29.14 R26.11 | length 581.1
  Bottom Layer w10: J29.14@2225,1200 2175,1150 2175,725 2200,700 R26.11@2250,700
B206: R26.6 U14.18 | length 577.5
  Top Layer w10: U14.18@2083.86,637.2 2137.2,637.2 2175,675 2175,725 2200,750 2525,750 2550,725 R26.6@2550,700
B207: J29.15 R26.10 | length 431.1
  Bottom Layer w10: R26.10@2250,800 2225,800 2200,825 2200,950 2225,975 2300,975 2325,1000 J29.15@2325,1100
B207: R26.7 U14.19 | length 665
  Top Layer w10: U14.19@2083.86,662.8 2134.51,662.8 2146.72,675 2146.72,821.72 2175,850 2525,850 2550,825 R26.7@2550,800
B208: J29.16 R26.9 | length 495.7
  Bottom Layer w10: R26.9@2250,900 2375,900 2400,925 2400,1175 2375,1200 J29.16@2325,1200
B208: R26.8 U14.20 | length 1205.8
  Top Layer w10: U14.20@2083.86,688.39 2038.39,688.39 2025,675 2025,625 2000,600 1950,600 1925,625 1925,925 1950,950 2525,950 2550,925 R26.8@2550,900
B209: R27.16 U15.4 | length 331.1
  Top Layer w10: R27.16@3150,900 3200,900 3225,875 3225,725 3236.02,713.98 U15.4@3316.14,713.98
B209: J30.1 R27.1 | length 445.7
  Bottom Layer w10: R27.1@2850,900 2850,1050 2900,1100 J30.1@3125,1100
B210: R27.15 U15.5 | length 256.3
  Top Layer w10: R27.15@3150,800 3175,800 3200,775 3200,700 3211.61,688.39 U15.5@3316.14,688.39
B210: J30.2 R27.2 | length 781.1
  Bottom Layer w10: R27.2@2850,800 2800,800 2775,825 2775,1150 2825,1200 J30.2@3125,1200
B211: R27.14 U15.6 | length 181.6
  Top Layer w10: R27.14@3150,700 3187.2,662.8 U15.6@3316.14,662.8
B211: J30.3 R27.3 | length 731.1
  Bottom Layer w10: R27.3@2850,700 2900,700 2925,725 2925,1000 2950,1025 3200,1025 3225,1050 J30.3@3225,1100
B212: R27.13 U15.7 | length 146.2
  Top Layer w10: 3175,625 3187.2,637.2 U15.7@3316.14,637.2
B212: J30.4 R27.4 | length 1095.7
  Top Layer w10: R27.4@2850,600 2925,600 2950,625 v1(2950,1275)
  Bottom Layer w10: v1(2950,1275) 3200,1275 3225,1250 J30.4@3225,1200
B213: R27.12 U15.8 | length 256.3
  Top Layer w10: R27.12@3150,500 3175,500 3200,525 3200,600 3211.61,611.61 U15.8@3316.14,611.61
B213: J30.5 R27.5 | length 1851.8
  Top Layer w10: R27.5@2850,500 3000,500 3025,525 3025,1275 3050,1300 3450,1300 3475,1275 3475,1050 3450,1025 3350,1025 3325,1050 J30.5@3325,1100
B214: R27.11 U15.9 | length 331.1
  Top Layer w10: R27.11@3150,400 3200,400 3225,425 3225,575 3236.02,586.02 U15.9@3316.14,586.02
B214: J30.6 R27.6 | length 1216.4
  Bottom Layer w10: R27.6@2850,400 3025,400 3050,425 3050,950 3075,975 3250,975 3275,1000 3275,1175 3300,1200 J30.6@3325,1200
B215: R27.10 U15.10 | length 405.8
  Top Layer w10: R27.10@3150,300 3225,300 3250,325 3250,550 3260.43,560.43 U15.10@3316.14,560.43
B215: J30.7 R27.7 | length 1331.1
  Bottom Layer w10: R27.7@2850,300 3050,300 3075,325 3075,925 3100,950 3400,950 3425,975 J30.7@3425,1100
B216: R27.9 U15.11 | length 648.3
  Top Layer w10: R27.9@3150,200 3200,200 3275,200 3300,200 3375,200 3400,225 3400,350 3400,375 3400,525 3390.16,534.84 U15.11@3316.14,534.84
